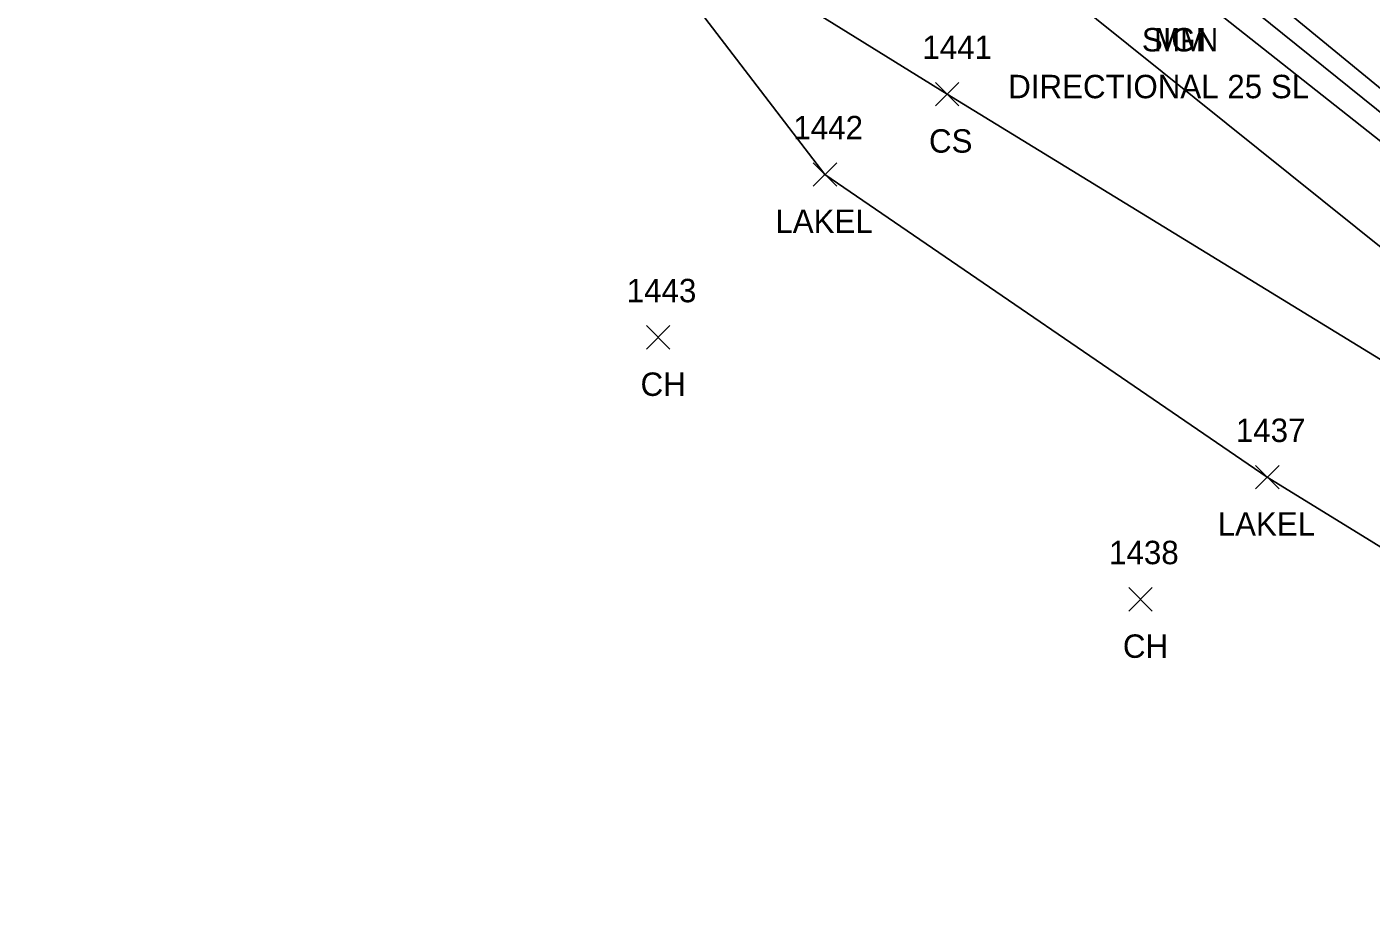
# Model space of a CAD drawing. Extents: x 1401404 to 1403982, y 557481 to 559873.
# Drawn here: x 1403022 to 1403136.9, y 558658.9 to 558734 of the extents above; entities that cross this region are included whole.
import ezdxf

# ---------------------------------------------------------------- set-up
doc = ezdxf.new("R2010")
doc.units = 0
for name, color, linetype in [('L_A', 7, 'Continuous'), ('L_I', 7, 'Continuous'), ('L_TIC', 7, 'Continuous'), ('LAWA', 7, 'Continuous'), ('LAWE', 7, 'Continuous'), ('LELB', 7, 'Continuous'), ('PET', 7, 'Continuous'), ('RGR', 7, 'Continuous'), ('S_A', 7, 'Continuous'), ('S_C', 7, 'Continuous')]:
    doc.layers.add(name, color=color, linetype=linetype)

msp = doc.modelspace()

# ---------------------------------------------------------------- linework, layer by layer
at = {"layer": 'L_TIC'}
for points in [[(1403099.63, 558727.29), (1403101.63, 558729.29)], [(1403101.63, 558727.29), (1403099.63, 558729.29)], [(1403089.18, 558720.43), (1403091.18, 558722.43)], [(1403091.18, 558720.43), (1403089.18, 558722.43)], [(1403074.93, 558706.51), (1403076.93, 558708.51)], [(1403076.93, 558706.51), (1403074.93, 558708.51)], [(1403126.98, 558694.57), (1403128.98, 558696.57)], [(1403128.98, 558694.57), (1403126.98, 558696.57)], [(1403116.15, 558684.13), (1403118.15, 558686.13)], [(1403118.15, 558684.13), (1403116.15, 558686.13)]]:
    msp.add_lwpolyline(points, dxfattribs=at)
at = {"layer": 'LAWA'}
msp.add_lwpolyline([(1403316.66, 558597.36), (1403281.73, 558613.91), (1403272.54, 558615.21), (1403248.23, 558629.23), (1403213.48, 558654.18), (1403180.64, 558681.31), (1403143.75, 558710.34), (1403107.91, 558739.1), (1403071.69, 558772.58), (1403068.31, 558766.93), (1403071.88, 558756.66), (1403070.51, 558749.44)], dxfattribs=at)
at = {"layer": 'LAWE'}
msp.add_lwpolyline([(1403238.68, 558611.56), (1403231.81, 558615.04), (1403202.57, 558639.47), (1403173.17, 558667.73), (1403127.98, 558695.57), (1403090.18, 558721.43), (1403068.99, 558749.07), (1403055.64, 558748.74), (1403047.53, 558763.16), (1403042.82, 558768.94)], dxfattribs=at)
at = {"layer": 'LELB'}
for points in [[(1403567.19, 558568.67), (1403521.33, 558570.05), (1403484.77, 558571.48), (1403436.83, 558574.71), (1403390.35, 558579.88), (1403360.17, 558585.19), (1403345.93, 558587.28), (1403333.51, 558592.26), (1403317.51, 558600.62), (1403299, 558608.83), (1403282.94, 558617.97), (1403248.09, 558638.93), (1403217.12, 558660.94), (1403185.33, 558684.7), (1403148.79, 558715.46), (1403112.06, 558744.49), (1403074.23, 558776.66), (1403055.65, 558783.75), (1403043.18, 558796.21), (1403041.06, 558801.07)], [(1403100.63, 558728.29), (1403083.1, 558739.17)], [(1403270.93, 558606.4), (1403261.72, 558609.88), (1403247.68, 558621.68), (1403207.96, 558643.77), (1403210.15, 558647.44), (1403209.07, 558648.44), (1403205.58, 558645.65), (1403178.43, 558674.04), (1403139.41, 558704.55), (1403100.63, 558728.29)]]:
    msp.add_lwpolyline(points, dxfattribs=at)
at = {"layer": 'PET'}
msp.add_lwpolyline([(1403567.32, 558571.16), (1403521.05, 558571.89), (1403485.08, 558573.95), (1403437.34, 558577.29), (1403390.93, 558583.55), (1403361.61, 558591.03), (1403321.82, 558602.54), (1403283.74, 558620.33), (1403244.19, 558645.3), (1403219.22, 558663.61), (1403205.44, 558672.12), (1403186.06, 558688.41), (1403150.64, 558718.11), (1403114.18, 558748.06), (1403076.2, 558780.03), (1403043.94, 558806.7), (1402997.13, 558841.77), (1402954.25, 558870.69), (1402915.87, 558893.53), (1402876.18, 558915.42), (1402801.33, 558955.21), (1402766.49, 558972.95)], dxfattribs=at)
at = {"layer": 'RGR'}
msp.add_lwpolyline([(1403343.04, 558588.83), (1403321.63, 558601.07), (1403283.23, 558619.58), (1403243.1, 558643.52), (1403218.12, 558661.74), (1403185.48, 558687.65), (1403149.87, 558716.9), (1403113.35, 558746.32), (1403075.03, 558778.37), (1403064.92, 558785.89), (1403057.13, 558787.17)], dxfattribs=at)

# ---------------------------------------------------------------- texts
at = {"layer": 'L_A'}
for s, p in [('CS', (1403099.07, 558723.29)), ('LAKEL', (1403085.94, 558716.43)), ('CH', (1403074.42, 558702.51)), ('LAKEL', (1403123.74, 558690.57)), ('CH', (1403115.64, 558680.13))]:
    msp.add_text(s, height=2, dxfattribs=at).set_placement(p)
at = {"layer": 'L_I'}
for s, p in [('1441', (1403098.5, 558731.29)), ('1442', (1403087.48, 558724.43)), ('1443', (1403073.24, 558710.51)), ('1437', (1403125.29, 558698.57)), ('1438', (1403114.46, 558688.13))]:
    msp.add_text(s, height=2, dxfattribs=at).set_placement(p)
at = {"layer": 'S_A'}
for s, p in [('SIGN', (1403117.26, 558731.94)), ('MM', (1403118.3, 558731.94))]:
    msp.add_text(s, height=2, dxfattribs=at).set_placement(p)
at = {"layer": 'S_C'}
msp.add_text('DIRECTIONAL 25 SL', height=2, dxfattribs=at).set_placement((1403105.84, 558727.94))

doc.saveas('drawing.dxf')
